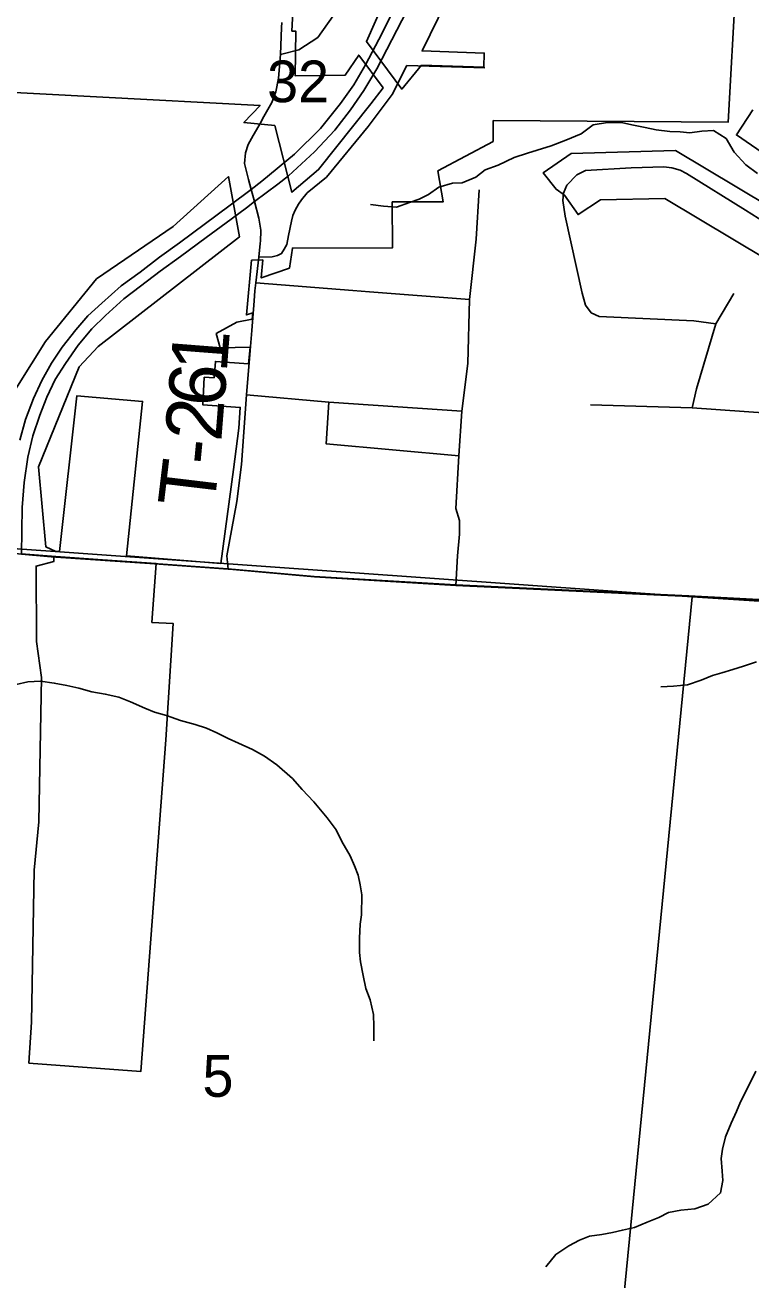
# Model space of a CAD drawing. Extents: x 0 to 34, y 0 to 22.
# Drawn here: x 27.717 to 28.447, y 19.082 to 20.344 of the extents above; entities that cross this region are included whole.
import ezdxf

# ---------------------------------------------------------------- set-up
doc = ezdxf.new("R2010")
doc.units = 0
for name, color, linetype in [('GM_X_City_Street', 7, 'Continuous'), ('GM_X_Corporation', 7, 'Continuous'), ('GM_X_Minor_River', 7, 'Continuous'), ('GM_X_Section_Text', 7, 'Continuous'), ('GM_X_State_Route', 7, 'Continuous'), ('GM_X_Township_Road', 7, 'Continuous'), ('GM_X_Township_Road_Text', 7, 'Continuous')]:
    doc.layers.add(name, color=color, linetype=linetype)

msp = doc.modelspace()

# ---------------------------------------------------------------- linework, layer by layer
at = {"layer": 'GM_X_City_Street'}
msp.add_line((28.101, 20.3038), (28.1792, 20.3014), dxfattribs=at)
for points in [[(27.974, 20.3147), (27.9924, 20.3196), (28.0113, 20.3318), (28.0268, 20.3535), (28.0332, 20.3726), (28.0345, 20.3943), (28.0378, 20.4106), (28.0477, 20.4249), (28.068, 20.4401), (28.1054, 20.4857)], [(28.6211, 19.9437), (28.6231, 19.9918), (28.6203, 20.0024), (28.616, 20.0095), (28.4861, 20.1301), (28.4414, 20.1581), (28.3821, 20.195), (28.3757, 20.1985), (28.3672, 20.2006), (28.3594, 20.2017), (28.3263, 20.2006), (28.2805, 20.1982), (28.2717, 20.1938), (28.2616, 20.1834)]]:
    msp.add_lwpolyline(points, dxfattribs=at)
at = {"layer": 'GM_X_Corporation'}
for points in [[(27.713, 19.8126), (27.7479, 19.8098), (27.921, 19.7976), (28.0078, 19.7898), (28.15, 19.7813), (28.3845, 19.7702), (28.4743, 19.7657), (28.6835, 19.7478), (28.7311, 19.743), (28.8977, 19.7297), (28.9889, 19.7198), (29.3495, 19.6807), (29.4353, 19.675), (29.5232, 19.6666), (30.3167, 19.5906), (30.3167, 20.9), (26.3743, 20.9)], [(27.624, 20.2809), (27.9533, 20.2636), (27.937, 20.2462), (27.9681, 20.2432), (27.9853, 20.1762), (28.0122, 20.199), (28.0648, 20.265), (28.077, 20.2813), (28.0526, 20.3142), (28.039, 20.2941), (27.9885, 20.2933), (27.9891, 20.3383), (27.9853, 20.3383), (27.9907, 20.4417)], [(28.1042, 20.4275), (28.0603, 20.3279), (28.0958, 20.28), (28.1157, 20.3041), (28.1783, 20.3019), (28.1787, 20.3161), (28.1162, 20.3183), (28.1722, 20.4332)], [(28.4317, 20.3852), (28.424, 20.2468), (28.1877, 20.2483), (28.1877, 20.2273), (28.132, 20.1976), (28.1375, 20.1667), (28.0862, 20.1665), (28.0863, 20.1203), (27.9859, 20.12), (27.9828, 20.0999), (27.9545, 20.0901), (27.956, 20.1082), (27.9447, 20.1079), (27.9396, 20.0529), (27.9461, 20.0549), (27.9455, 20.0484), (27.9299, 20.0457), (27.9093, 20.0343), (27.9131, 20.0196), (27.9432, 20.0205), (27.9418, 20.0037), (27.9084, 20.006), (27.907, 19.9897), (27.8972, 19.9901), (27.8956, 19.9625), (27.9334, 19.9598), (27.932, 19.939), (27.9267, 19.8975), (27.9139, 19.803), (27.8191, 19.8104), (27.8352, 19.9659), (27.7691, 19.9715), (27.7517, 19.8148), (27.7478, 19.8148), (27.7379, 19.8195), (27.7305, 19.9002), (27.7713, 20.0007), (27.7904, 20.0211), (27.9325, 20.1313), (27.9215, 20.1919), (27.8659, 20.1419), (27.789, 20.0891), (27.7377, 20.0262), (27.6953, 19.9588)], [(28.4486, 20.259), (28.4322, 20.2339), (28.5023, 20.1858)], [(28.4959, 20.1434), (28.3709, 20.2181), (28.2661, 20.2153), (28.2381, 20.1958), (28.2509, 20.1792), (28.2594, 20.1732), (28.273, 20.1537), (28.2957, 20.1685), (28.3604, 20.1698), (28.4629, 20.1086)], [(30.3167, 14.1), (30.3167, 19.5906), (29.5232, 19.6666), (29.4353, 19.675), (29.3495, 19.6807), (28.9889, 19.7198), (28.8977, 19.7297), (28.7311, 19.743), (28.6835, 19.7478), (28.4743, 19.7657), (28.3845, 19.7702), (28.15, 19.7813), (28.0078, 19.7898), (27.921, 19.7976), (27.7479, 19.8098), (27.713, 19.8126)]]:
    msp.add_lwpolyline(points, dxfattribs=at)
for points in [[(27.5018, 20.8365), (28.5465, 20.7695), (28.4917, 19.7627), (28.3876, 19.7694), (27.4311, 19.8373)], [(27.4311, 19.8373), (28.3876, 19.7694), (28.2889, 18.7562), (27.2938, 18.8276), (27.3834, 19.8411)], [(27.7459, 19.81), (27.8488, 19.8027), (27.8446, 19.7435), (27.866, 19.7424), (27.8586, 19.6255), (27.8335, 19.292), (27.7209, 19.3004), (27.7235, 19.3416), (27.7261, 19.4945), (27.7308, 19.543), (27.7335, 19.6881), (27.7286, 19.7244), (27.7281, 19.8003), (27.7459, 19.8047)], [(28.4917, 19.7627), (29.3585, 19.6871), (29.2972, 18.6715), (28.6566, 18.7331), (28.2889, 18.7562), (28.3876, 19.7694)]]:
    msp.add_lwpolyline(points, close=True, dxfattribs=at)
at = {"layer": 'GM_X_Minor_River'}
for points in [[(28.4536, 20.1951), (28.4416, 20.2039), (28.4299, 20.2165), (28.4221, 20.2302), (28.4092, 20.2382), (28.3975, 20.2376), (28.3854, 20.2361), (28.3756, 20.2369), (28.3653, 20.2374), (28.3514, 20.239), (28.3404, 20.2414), (28.3272, 20.2441), (28.3166, 20.2464), (28.3026, 20.2462), (28.2882, 20.244), (28.276, 20.235), (28.2608, 20.2286), (28.2461, 20.223), (28.232, 20.2186), (28.2222, 20.2156), (28.2089, 20.2111), (28.1926, 20.2033), (28.1797, 20.1988), (28.1702, 20.1913), (28.1565, 20.1857), (28.1467, 20.1854), (28.133, 20.1813), (28.1227, 20.1738), (28.1132, 20.1693), (28.1034, 20.1659), (28.0905, 20.1611), (28.0773, 20.1623), (28.0644, 20.1639)], [(28.4525, 19.7039), (28.4393, 19.6995), (28.4286, 19.6961), (28.4176, 19.6928), (28.4082, 19.6902), (28.3968, 19.6854), (28.3831, 19.6809), (28.3691, 19.6795), (28.3562, 19.6788)], [(27.7081, 19.6812), (27.7198, 19.6838), (27.7327, 19.6845)], [(27.7327, 19.6845), (27.7463, 19.6825), (27.7591, 19.6801), (27.7712, 19.6774), (27.7841, 19.6739), (27.7977, 19.6715), (27.8113, 19.6684), (27.823, 19.6638), (27.8373, 19.6572), (27.8471, 19.6534), (27.8592, 19.6499), (27.8732, 19.6449), (27.8879, 19.641), (27.8996, 19.6371), (27.9098, 19.6325), (27.9211, 19.6267), (27.9317, 19.6221), (27.9456, 19.6159), (27.9577, 19.609), (27.9701, 19.6002), (27.9859, 19.5865), (27.9957, 19.5754), (28.0073, 19.5632), (28.0208, 19.5472), (28.0298, 19.535), (28.0354, 19.5232), (28.044, 19.5087), (28.0481, 19.4988), (28.0519, 19.4893), (28.0541, 19.4798), (28.0555, 19.4696), (28.0554, 19.4495), (28.0538, 19.44), (28.0533, 19.426), (28.0532, 19.4116), (28.0543, 19.4021), (28.0568, 19.3884), (28.0598, 19.3755), (28.0639, 19.3641), (28.0672, 19.3493), (28.0678, 19.3371), (28.0677, 19.3227)], [(28.4516, 19.2924), (28.4466, 19.2819), (28.4363, 19.2615), (28.4324, 19.2516), (28.427, 19.2399), (28.4213, 19.2263), (28.4182, 19.2138), (28.417, 19.2043), (28.418, 19.1918), (28.4187, 19.1823), (28.4164, 19.1698), (28.4038, 19.1585), (28.3905, 19.1537), (28.3765, 19.1526), (28.364, 19.1501), (28.3541, 19.1452), (28.3424, 19.1403), (28.3298, 19.1351), (28.3177, 19.1325), (28.3075, 19.13), (28.2969, 19.1281), (28.2844, 19.1263), (28.2745, 19.1222), (28.2639, 19.1166), (28.2506, 19.108), (28.2406, 19.0955)]]:
    msp.add_lwpolyline(points, dxfattribs=at)
at = {"layer": 'GM_X_State_Route'}
for p, q in [((27.9476, 20.1668), (27.971, 20.1844)), ((27.9395, 20.1607), (27.9476, 20.1668))]:
    msp.add_line(p, q, dxfattribs=at)
for points in [[(27.971, 20.1844), (27.9819, 20.1926), (28.0081, 20.2168), (28.0285, 20.2387), (28.0443, 20.2592), (28.0576, 20.2786), (28.0706, 20.3002), (28.1007, 20.3587), (28.1434, 20.444), (28.1563, 20.4673), (28.1683, 20.4869), (28.1808, 20.5027), (28.1961, 20.52), (28.2109, 20.5336), (28.2146, 20.5369)], [(27.7118, 19.927), (27.7173, 19.9477), (27.7255, 19.9689), (27.7339, 19.9869), (27.7436, 20.0043), (27.7544, 20.0203), (27.7679, 20.0377), (27.7801, 20.0519), (27.7941, 20.0648), (27.8138, 20.082), (27.8326, 20.0959), (27.8523, 20.1109), (27.8724, 20.1252), (27.9232, 20.1631), (27.9443, 20.179), (27.9551, 20.1872), (27.9879, 20.2145), (28.0139, 20.2402), (28.0342, 20.2655), (28.0477, 20.2843), (28.0593, 20.3044), (28.076, 20.3361), (28.0946, 20.3736)], [(27.8991, 20.1306), (27.9242, 20.149), (27.9395, 20.1607)], [(27.7133, 19.8121), (27.7141, 19.859), (27.7161, 19.8843), (27.7199, 19.9098), (27.7248, 19.9314), (27.732, 19.9519), (27.7389, 19.97), (27.7473, 19.988), (27.7577, 20.0041), (27.7705, 20.0224), (27.7843, 20.0388), (27.7978, 20.0521), (27.8163, 20.0689), (27.833, 20.0816), (27.8528, 20.097), (27.8732, 20.1115), (27.8991, 20.1306)]]:
    msp.add_lwpolyline(points, dxfattribs=at)
at = {"layer": 'GM_X_Township_Road'}
for p, q in [((27.9536, 20.1274), (27.9541, 20.1372)), ((27.9489, 20.085), (28.0467, 20.0774)), ((27.9449, 20.0371), (27.9474, 20.067)), ((27.9474, 20.067), (27.9482, 20.077)), ((27.9432, 20.0172), (27.9449, 20.0371))]:
    msp.add_line(p, q, dxfattribs=at)
for points in [[(27.9543, 20.2471), (27.9559, 20.2499), (27.9651, 20.2666), (27.9692, 20.2773), (27.9717, 20.2908), (27.974, 20.3147), (27.975, 20.3418), (27.9753, 20.3469)], [(27.9521, 20.1109), (27.9654, 20.1114), (27.9709, 20.1127), (27.975, 20.1147), (27.9776, 20.119), (27.9801, 20.1235), (27.9819, 20.1328), (27.9849, 20.1471), (27.9863, 20.1527), (27.9885, 20.1583), (27.9918, 20.1641), (27.9951, 20.1685), (28.0005, 20.1755), (28.0202, 20.1915), (28.0621, 20.2425), (28.0861, 20.2746), (28.101, 20.3038)], [(27.9541, 20.1372), (27.9542, 20.1382), (27.952, 20.15), (27.9476, 20.1668), (27.9443, 20.179), (27.9416, 20.189), (27.9375, 20.205), (27.9386, 20.216), (27.9414, 20.2244), (27.9462, 20.2332), (27.9543, 20.2471)], [(28.4116, 20.0439), (28.3894, 20.0468), (28.2942, 20.0512), (28.2863, 20.055), (28.2805, 20.0626), (28.277, 20.0746), (28.26, 20.1523), (28.2577, 20.1678), (28.2583, 20.1754), (28.2616, 20.1834)], [(28.1501, 19.858), (28.1532, 19.9112), (28.1562, 19.956), (28.1622, 20.004), (28.164, 20.0682), (28.1705, 20.129), (28.1735, 20.1786)], [(27.9482, 20.077), (27.9489, 20.085), (27.9521, 20.1109), (27.9535, 20.1245), (27.9536, 20.1274)], [(28.0467, 20.0774), (28.0633, 20.0761), (28.164, 20.0682)], [(28.3877, 19.9595), (28.3921, 19.9784), (28.4116, 20.0439), (28.4298, 20.0743)], [(27.9212, 19.7971), (27.9199, 19.8105), (27.9299, 19.8652), (27.9346, 19.9024), (27.9395, 19.9724), (27.9432, 20.0172)], [(27.9395, 19.9724), (28.0224, 19.965), (28.1562, 19.956)], [(28.0224, 19.965), (28.0197, 19.9232), (28.1532, 19.9112)], [(28.5684, 19.9468), (28.3877, 19.9595), (28.2855, 19.9623)], [(28.1502, 19.7808), (28.1519, 19.8104), (28.1539, 19.8325), (28.1537, 19.846), (28.1501, 19.858)], [(27.593, 19.8243), (27.6009, 19.8236), (27.6885, 19.8145), (27.7012, 19.8134), (27.7133, 19.8121), (27.7431, 19.8097)], [(27.7431, 19.8097), (27.7481, 19.8093), (27.8426, 19.8027)], [(27.8426, 19.8027), (27.9212, 19.7971), (27.9222, 19.797)], [(27.9222, 19.797), (28.008, 19.7893), (28.1502, 19.7808), (28.3847, 19.7696), (28.4745, 19.7652), (28.6838, 19.7473), (28.7313, 19.7425), (28.8979, 19.7292)]]:
    msp.add_lwpolyline(points, dxfattribs=at)

# ---------------------------------------------------------------- texts
at = {"layer": 'GM_X_Section_Text'}
for s, height, p in [('32', 0.04186, (27.9604, 20.2668)), ('5', 0.0419, (27.8954, 19.2665))]:
    msp.add_text(s, height=height, rotation=0, dxfattribs=at).set_placement(p)
at = {"layer": 'GM_X_Township_Road_Text'}
for s, rotation, p in [('1', 85.568, (27.9197, 19.9941)), ('6', 85.5637, (27.917, 19.9594)), ('2', 85.4371, (27.9142, 19.9247)), ('-', 84.5657, (27.9119, 19.9007)), ('T', 83.1828, (27.9068, 19.8571))]:
    msp.add_text(s, height=0.0568, rotation=rotation, dxfattribs=at).set_placement(p)

doc.saveas('drawing.dxf')
